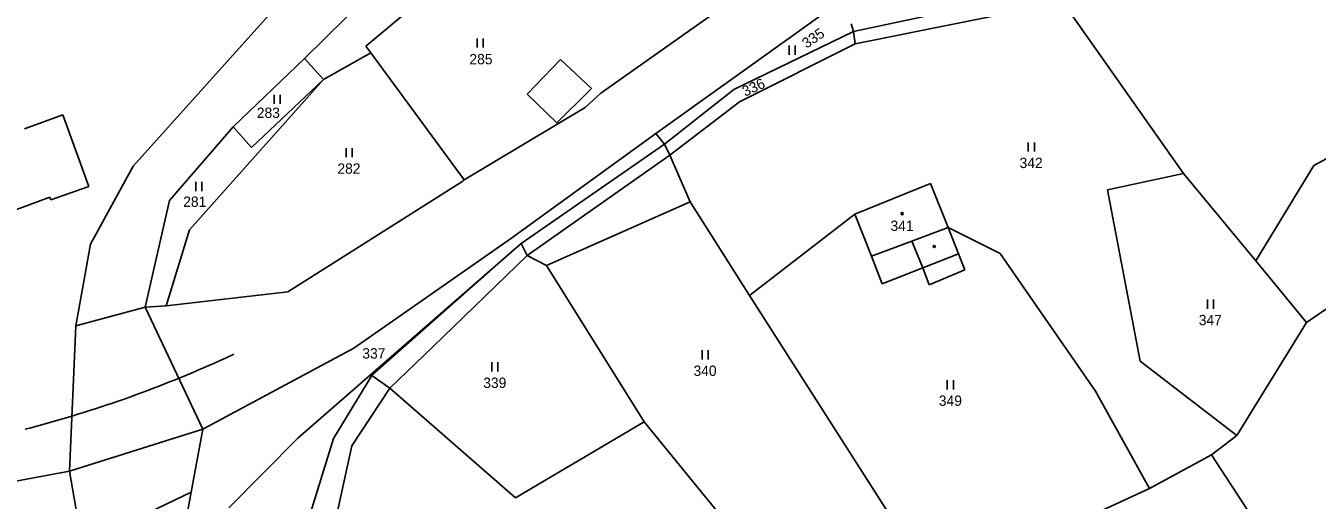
# Model space of a CAD drawing. Extents: x -670359 to -668019, y -978807 to -976674.
# Drawn here: x -669241.5 to -669029.4, y -977159.1 to -977081.3 of the extents above; entities that cross this region are included whole.
import ezdxf

# ---------------------------------------------------------------- set-up
doc = ezdxf.new("R2010")
doc.units = 0
for name, color, linetype in [('Hranice parcel', 7, 'Continuous'), ('Navazující stavba', 7, 'Continuous'), ('Parcelní čísla', 7, 'Continuous'), ('Související stavba', 7, 'Continuous'), ('Vnitřní kresba', 7, 'Continuous'), ('Značky budov', 7, 'Continuous'), ('Značky kultur', 7, 'Continuous')]:
    doc.layers.add(name, color=color, linetype=linetype)

msp = doc.modelspace()

# ---------------------------------------------------------------- linework, layer by layer
at = {"layer": 'Hranice parcel'}
for points in [[(-669175.21, -977066.43), (-669195.69, -977086.62)], [(-669170.18, -977071.73), (-669185.64, -977084.61)], [(-669070.99, -977074.8), (-669105.55, -977082.22)], [(-669147.03, -977092.35), (-669124.88, -977076.65)], [(-669200.15, -977077.96), (-669223.85, -977104.3)], [(-669108.55, -977077.9), (-669116.1, -977083.32)], [(-669071.17, -977077.39), (-669105.25, -977084.23)], [(-669071.17, -977077.39), (-669051.32, -977105.5)], [(-669105.55, -977082.22), (-669105.92, -977080.95)], [(-669116.1, -977083.32), (-669138.01, -977098.94)], [(-669105.55, -977082.22), (-669125.16, -977091.74)], [(-669105.25, -977084.23), (-669105.55, -977082.22)], [(-669185.64, -977084.61), (-669184.8, -977085.69)], [(-669105.25, -977084.23), (-669124.27, -977093.72)], [(-669029.93, -977104.2), (-668995.44, -977085.57)], [(-669195.69, -977086.62), (-669207.42, -977097.87)], [(-669192.58, -977090.07), (-669195.69, -977086.62)], [(-669184.8, -977085.69), (-669192.58, -977090.07)], [(-669184.8, -977085.69), (-669169.48, -977106.54)], [(-669192.58, -977090.07), (-669214.6, -977114.73)], [(-669192.58, -977090.07), (-669204.39, -977101.23)], [(-669125.16, -977091.74), (-669136.58, -977100.7)], [(-669149.6, -977094.67), (-669147.03, -977092.35)], [(-669124.27, -977093.72), (-669135.69, -977102.51)], [(-669235.38, -977095.86), (-669241.7, -977098.19)], [(-669231.13, -977107.63), (-669235.38, -977095.86)], [(-669169.48, -977106.54), (-669149.6, -977094.67)], [(-669207.42, -977097.87), (-669217.87, -977109.92)], [(-669204.39, -977101.23), (-669207.42, -977097.87)], [(-669138.01, -977098.94), (-669161.84, -977116.23)], [(-669136.58, -977100.7), (-669138.01, -977098.94)], [(-669136.58, -977100.7), (-669160.1, -977117)], [(-669135.69, -977102.51), (-669136.58, -977100.7)], [(-669135.69, -977102.51), (-669132.36, -977110.16)], [(-669223.85, -977104.3), (-669230.86, -977117.08)], [(-669039.43, -977119.85), (-669029.93, -977104.2)], [(-669198.42, -977124.93), (-669169.67, -977106.76)], [(-669169.67, -977106.76), (-669169.48, -977106.54)], [(-669051.32, -977105.5), (-669063.82, -977108.18)], [(-669051.32, -977105.5), (-669039.43, -977119.85)], [(-669237.37, -977109.84), (-669231.13, -977107.63)], [(-669092.88, -977107.14), (-669105.3, -977112.15)], [(-669090, -977114.38), (-669092.88, -977107.14)], [(-669063.82, -977108.18), (-669058.46, -977136.28)], [(-669276.7, -977123.85), (-669237.53, -977109.41)], [(-669237.53, -977109.41), (-669237.37, -977109.84)], [(-669217.87, -977109.92), (-669221.85, -977127.43)], [(-669132.36, -977110.16), (-669122.64, -977125.54)], [(-669105.3, -977112.15), (-669122.64, -977125.54)], [(-669102.6, -977119.04), (-669105.3, -977112.15)], [(-669214.6, -977114.73), (-669218.41, -977127.2)], [(-669081.46, -977118.62), (-669090, -977114.38)], [(-669090, -977114.38), (-669088.28, -977118.68)], [(-669230.86, -977117.08), (-669233.23, -977130.52)], [(-669196.78, -977148.94), (-669160.1, -977117)], [(-669161.84, -977116.23), (-669187.58, -977134.18)], [(-669160.1, -977117), (-669184.66, -977138.65)], [(-669160.1, -977117), (-669159.13, -977118.96)], [(-669159.13, -977118.96), (-669155.93, -977120.57)], [(-669100.81, -977123.61), (-669102.6, -977119.04)], [(-669088.28, -977118.68), (-669094.12, -977120.98)], [(-669065.77, -977141.22), (-669081.46, -977118.62)], [(-669155.93, -977120.57), (-669139.93, -977146.22)], [(-669094.12, -977120.98), (-669100.81, -977123.61)], [(-669039.43, -977119.85), (-669031.15, -977129.95)], [(-669218.41, -977127.2), (-669198.42, -977124.93)], [(-669122.64, -977125.54), (-669092.76, -977172.16)], [(-669233.23, -977130.52), (-669221.85, -977127.43)], [(-669221.85, -977127.43), (-669218.41, -977127.2)], [(-669031.15, -977129.95), (-669025.76, -977126.29)], [(-669042.57, -977148.49), (-669031.15, -977129.95)], [(-669187.58, -977134.18), (-669212.37, -977147.43)], [(-669058.46, -977136.28), (-669042.57, -977148.49)], [(-669190.94, -977148.96), (-669184.66, -977138.65)], [(-669184.66, -977138.65), (-669181.7, -977140.74)], [(-669181.7, -977140.74), (-669161.03, -977158.72)], [(-669065.77, -977141.22), (-669056.93, -977157.17)], [(-669161.03, -977158.72), (-669139.93, -977146.22)], [(-669139.93, -977146.22), (-669116.72, -977174.68)], [(-669234.31, -977154.34), (-669212.37, -977147.43)], [(-669212.37, -977147.43), (-669214.32, -977157.79)], [(-669208.11, -977160.35), (-669196.78, -977148.94)], [(-669194.66, -977161.03), (-669190.94, -977148.96)], [(-669046.76, -977151.63), (-669042.57, -977148.49)], [(-669056.93, -977157.17), (-669046.76, -977151.63)], [(-669046.76, -977151.63), (-669025.88, -977183.58)], [(-669244.61, -977156.24), (-669234.31, -977154.34)], [(-669082.92, -977169.18), (-669056.93, -977157.17)], [(-669214.32, -977157.79), (-669215.81, -977165.77)]]:
    msp.add_lwpolyline(points, dxfattribs=at)
at = {"layer": 'Navazující stavba'}
msp.add_lwpolyline([(-669241.59, -977147.46), (-669240.63, -977147.21), (-669239.66, -977146.95), (-669238.7, -977146.69), (-669237.73, -977146.42), (-669236.77, -977146.15), (-669235.81, -977145.87), (-669234.85, -977145.59), (-669233.89, -977145.3), (-669232.93, -977145.01), (-669231.98, -977144.71), (-669231.03, -977144.41), (-669230.07, -977144.1), (-669229.12, -977143.79), (-669228.17, -977143.48), (-669227.23, -977143.16), (-669226.28, -977142.83), (-669225.34, -977142.5), (-669224.39, -977142.17), (-669223.45, -977141.83), (-669222.51, -977141.49), (-669221.58, -977141.14), (-669220.64, -977140.79), (-669219.71, -977140.43), (-669218.78, -977140.07), (-669217.85, -977139.7), (-669216.92, -977139.33), (-669215.99, -977138.95), (-669215.07, -977138.57), (-669214.14, -977138.18), (-669213.22, -977137.79), (-669212.3, -977137.4), (-669211.39, -977137), (-669210.47, -977136.6), (-669209.56, -977136.19), (-669208.65, -977135.78), (-669207.28, -977135.15)], dxfattribs=at)
at = {"layer": 'Související stavba'}
msp.add_lwpolyline([(-669241.59, -977147.46), (-669240.63, -977147.21), (-669239.66, -977146.95), (-669238.7, -977146.69), (-669237.73, -977146.42), (-669236.77, -977146.15), (-669235.81, -977145.87), (-669234.85, -977145.59), (-669233.89, -977145.3), (-669232.93, -977145.01), (-669231.98, -977144.71), (-669231.03, -977144.41), (-669230.07, -977144.1), (-669229.12, -977143.79), (-669228.17, -977143.48), (-669227.23, -977143.16), (-669226.28, -977142.83), (-669225.34, -977142.5), (-669224.39, -977142.17), (-669223.45, -977141.83), (-669222.51, -977141.49), (-669221.58, -977141.14), (-669220.64, -977140.79), (-669219.71, -977140.43), (-669218.78, -977140.07), (-669217.85, -977139.7), (-669216.92, -977139.33), (-669215.99, -977138.95), (-669215.07, -977138.57), (-669214.14, -977138.18), (-669213.22, -977137.79), (-669212.3, -977137.4), (-669211.39, -977137), (-669210.47, -977136.6), (-669209.56, -977136.19), (-669208.65, -977135.78), (-669207.28, -977135.15)], dxfattribs=at)
at = {"layer": 'Vnitřní kresba'}
for points in [[(-669159.12, -977092.48), (-669153.66, -977086.81)], [(-669153.66, -977086.81), (-669148.55, -977091.55)], [(-669149.03, -977092.03), (-669154.25, -977097.21)], [(-669148.55, -977091.55), (-669149.03, -977092.03)], [(-669154.25, -977097.21), (-669159.12, -977092.48)], [(-669159.13, -977118.96), (-669135.69, -977102.51)], [(-669155.93, -977120.57), (-669132.36, -977110.16)], [(-669095.95, -977116.58), (-669090, -977114.38)], [(-669102.6, -977119.04), (-669095.95, -977116.58)], [(-669095.95, -977116.58), (-669094.12, -977120.98)], [(-669159.13, -977118.96), (-669174.63, -977133.96)], [(-669087.24, -977121.32), (-669088.28, -977118.68)], [(-669094.12, -977120.98), (-669093.09, -977123.79)], [(-669093.09, -977123.79), (-669087.24, -977121.32)], [(-669221.85, -977127.43), (-669212.37, -977147.43)], [(-669233.23, -977130.52), (-669234.31, -977154.34)], [(-669174.63, -977133.96), (-669181.7, -977140.74)], [(-669187.9, -977150.17), (-669181.7, -977140.74)], [(-669190.5, -977161.92), (-669187.9, -977150.17)], [(-669234.31, -977154.34), (-669232.23, -977166.36)], [(-669232.23, -977166.36), (-669214.32, -977157.79)]]:
    msp.add_lwpolyline(points, dxfattribs=at)
at = {"layer": 'Značky budov'}
msp.add_circle((-669097.55, -977112.09), 0.175, dxfattribs=at)
at = {"layer": 'Značky kultur'}
for p, q in [((-669167.33, -977083.35), (-669167.33, -977084.85)), ((-669166.33, -977084.85), (-669166.33, -977083.35)), ((-669116.1, -977084.52), (-669116.1, -977086.02)), ((-669115.1, -977086.02), (-669115.1, -977084.52)), ((-669200.67, -977092.57), (-669200.67, -977094.07)), ((-669199.67, -977094.07), (-669199.67, -977092.57)), ((-669076.83, -977100.41), (-669076.83, -977101.91)), ((-669075.83, -977101.91), (-669075.83, -977100.41)), ((-669188.87, -977101.34), (-669188.87, -977102.84)), ((-669187.87, -977102.84), (-669187.87, -977101.34)), ((-669213.55, -977106.88), (-669213.55, -977108.38)), ((-669212.55, -977108.38), (-669212.55, -977106.88)), ((-669047.4, -977126.19), (-669047.4, -977127.69)), ((-669046.4, -977127.69), (-669046.4, -977126.19)), ((-669164.95, -977136.48), (-669164.95, -977137.98)), ((-669163.95, -977137.98), (-669163.95, -977136.48)), ((-669130.38, -977134.51), (-669130.38, -977136.01)), ((-669129.38, -977136.01), (-669129.38, -977134.51)), ((-669090.13, -977139.42), (-669090.13, -977140.92)), ((-669089.13, -977140.92), (-669089.13, -977139.42))]:
    msp.add_line(p, q, dxfattribs=at)
for centre in [(-669097.55, -977112.09), (-669092.27, -977117.47)]:
    msp.add_circle(centre, 0.175, dxfattribs=at)

# ---------------------------------------------------------------- texts
at = {"layer": 'Parcelní čísla'}
for s, rotation, p in [('335', 34.2869, (-669113.24, -977085.05)), ('336', 24.8314, (-669123.32, -977092.92))]:
    msp.add_text(s, height=1.7, rotation=rotation, dxfattribs=at).set_placement(p)
for s, p in [('285', (-669168.61, -977087.59)), ('283', (-669203.53, -977096.39)), ('282', (-669190.3, -977105.54)), ('342', (-669078.26, -977104.61)), ('281', (-669215.62, -977110.98)), ('341', (-669099.46, -977114.93)), ('347', (-669048.83, -977130.39)), ('337', (-669186.2, -977135.86)), ('340', (-669131.81, -977138.71)), ('339', (-669166.34, -977140.68)), ('349', (-669091.52, -977143.62))]:
    msp.add_text(s, height=1.7, dxfattribs=at).set_placement(p)

doc.saveas('drawing.dxf')
